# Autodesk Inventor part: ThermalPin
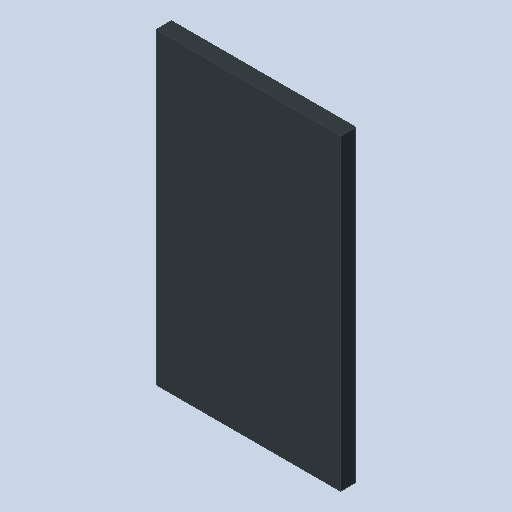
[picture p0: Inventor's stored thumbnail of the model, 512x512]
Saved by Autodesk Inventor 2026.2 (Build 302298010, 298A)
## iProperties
Created: 2026-10
Part Number: ThermalPin
Material: Générique
Document SubType Name: Modeling
Designer: mel
Density: 1 g/cm^3
Appearance: Par défaut
Author: mel
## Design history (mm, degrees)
feature "Base1"
node "Solide1"
